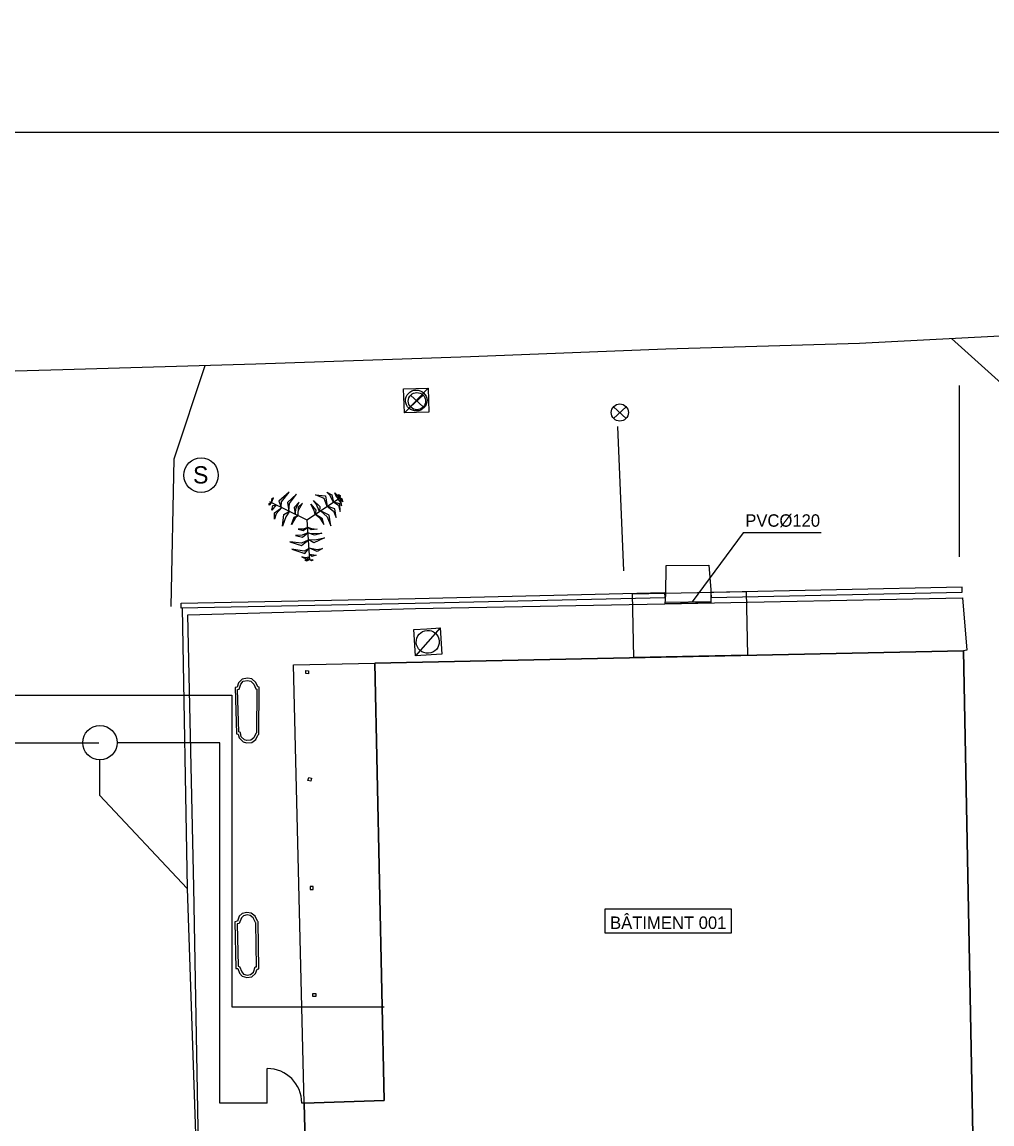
# Model space of a CAD drawing. Extents: x 37864 to 38032, y 453991 to 454052.
# Drawn here: x 37980.79 to 38008.9, y 454019.49 to 454051.41 of the extents above; entities that cross this region are included whole.
import ezdxf

# ---------------------------------------------------------------- set-up
doc = ezdxf.new("R2010")
doc.units = 0
for name, color, linetype in [('GO MUR EXTERIEUR', 7, 'Continuous'), ('GO_MUR_INTERIEUR', 7, 'Continuous'), ('PS_Bolt', 7, 'Continuous'), ('PS_Const', 7, 'Continuous'), ('PS_Dim', 7, 'Continuous'), ('PS_Elev_flag', 7, 'Continuous'), ('PS_Hatch', 7, 'Continuous'), ('PS_Hidden', 7, 'Continuous'), ('PS_Mid', 7, 'Continuous'), ('PS_Plate', 7, 'Continuous'), ('PS_Solid', 7, 'Continuous'), ('PS_Text', 7, 'Continuous'), ('SO_MENUISERIE EXT DOR', 7, 'Continuous'), ('SO_MENUISERIE INT DOR', 7, 'Continuous'), ('SO_SANITAIRE DETAILLE', 7, 'Continuous')]:
    doc.layers.add(name, color=color, linetype=linetype)

# ---------------------------------------------------------------- blocks, each defined once
blk = doc.blocks.new('PANNEAU')
blk.add_circle((0, 0), 0.5)
blk.add_text('S', height=0.5).set_placement((-0.233, -0.24))
blk = doc.blocks.new('A-REGARD')
for p, q in [((0, 1), (1, 1)), ((0, 0), (1, 1)), ((0, 0), (0, 1)), ((1, 1), (1, 0)), ((0.5, 0), (0, 0)), ((1, 0), (0.5, 0))]:
    blk.add_line(p, q)
blk.add_circle((0.5, 0.5), 0.438)
blk = doc.blocks.new('CONIFERE')
for p, q in [((0, 0), (0.976, 0.647)), ((-1.078, 0.532), (0, 0)), ((0, 0), (0.08, -1.165))]:
    blk.add_line(p, q)
for points in [[(-0.741, 0.364), (-0.739, 0.523), (-0.511, 0.797), (-0.811, 0.54)], [(-0.519, 0.261), (-0.499, 0.472), (-0.295, 0.746), (-0.559, 0.501)], [(0.588, 0.387), (0.498, 0.618), (0.255, 0.727), (0.538, 0.69)], [(0.768, 0.507), (0.663, 0.715), (0.579, 0.797), (0.722, 0.721)], [(0.913, 0.604), (0.84, 0.707), (0.816, 0.777), (0.899, 0.693)], [(0.956, 0.633), (0.917, 0.732), (0.966, 0.705)], [(-1.023, 0.503), (-1.089, 0.42), (-1.091, 0.475)], [(-1.025, 0.504), (-0.971, 0.637), (-1.021, 0.589)], [(-0.888, 0.436), (-1.016, 0.279), (-0.985, 0.411)], [(-0.721, 0.354), (-0.891, 0.168), (-0.941, 0.021), (-0.939, 0.198)], [(-0.335, 0.164), (-0.311, 0.342), (-0.22, 0.506), (-0.364, 0.356)], [(-0.262, 0.122), (-0.241, 0.278), (-0.128, 0.485), (-0.248, 0.367)], [(0.245, 0.158), (0.215, 0.27), (0.111, 0.452), (0.259, 0.279)], [(0.371, 0.242), (0.267, 0.463), (0.197, 0.562), (0.378, 0.385)], [(0.59, 0.394), (0.775, 0.253), (0.851, 0.066), (0.809, 0.322)], [(0.782, 0.51), (0.919, 0.422), (0.966, 0.236), (0.956, 0.46)], [(0.907, 0.587), (0.977, 0.501), (1.009, 0.403), (0.992, 0.558)], [(0.958, 0.634), (1.046, 0.52), (1.029, 0.588)], [(-0.506, 0.248), (-0.606, 0.089), (-0.702, -0.183), (-0.666, 0.155)], [(-0.256, 0.125), (-0.338, 0.043), (-0.443, -0.139), (-0.368, 0.076)], [(0.246, 0.164), (0.37, 0.069), (0.493, -0.134), (0.451, 0.03)], [(0.394, 0.257), (0.593, 0.086), (0.691, -0.173), (0.65, 0.13)], [(0.018, -0.223), (-0.1, -0.27), (-0.255, -0.267), (-0.103, -0.306)], [(0.018, -0.218), (0.131, -0.256), (0.297, -0.27), (0.128, -0.295)], [(0.037, -0.588), (-0.156, -0.676), (-0.495, -0.637), (-0.152, -0.743)], [(0.029, -0.381), (-0.138, -0.448), (-0.325, -0.452), (-0.124, -0.502)], [(0.029, -0.376), (0.157, -0.398), (0.437, -0.392), (0.22, -0.442)], [(0.041, -0.571), (0.229, -0.578), (0.512, -0.525), (0.202, -0.663)], [(0.058, -0.832), (-0.08, -0.91), (-0.431, -0.849), (-0.059, -0.981)], [(0.057, -0.81), (0.303, -0.864), (0.456, -0.834), (0.301, -0.92)], [(0.064, -1.081), (-0.046, -1.098), (-0.147, -1.076), (-0.004, -1.14)], [(0.079, -1.149), (-0.063, -1.168), (0.004, -1.187)], [(0.069, -0.995), (0.269, -1.028), (0.14, -1.067)], [(0.079, -1.146), (0.184, -1.162), (0.137, -1.191)]]:
    blk.add_lwpolyline(points, close=True)
blk = doc.blocks.new('BORNANTI')
for p, q in [((-0.369, -0.338), (0.369, 0.338)), ((-0.369, 0.338), (0.369, -0.338))]:
    blk.add_line(p, q)
blk.add_circle((0, 0), 0.5)
blk = doc.blocks.new('DIVERS-P')
blk.add_circle((0, 0), 0.5)

msp = doc.modelspace()

# ---------------------------------------------------------------- linework, layer by layer
at = {"layer": 'DEFPOINTS'}
msp.add_lwpolyline([(37950.431, 453990.816), (38032.431, 453990.816), (38032.431, 454048.216), (37950.431, 454048.216)], close=True, dxfattribs=at)
at = {"layer": 'GO MUR EXTERIEUR'}
for points in [[(37991.018, 454032.841), (37991.287, 454020.167), (37988.97, 454020.093), (37989.052, 454016.74), (38008.383, 454017.171), (38008.074, 454033.195)], [(37997.689, 454025.723), (38001.343, 454025.723), (38001.343, 454025.015), (37997.689, 454025.015)]]:
    msp.add_lwpolyline(points, close=True, dxfattribs=at)
at = {"layer": 'GO_MUR_INTERIEUR'}
msp.add_line((37999.44, 454034.608), (38000.76, 454034.623), dxfattribs=at)
msp.add_lwpolyline([(37985.426, 454034.436), (37985.576, 454026.312), (37985.9, 454016.645)], dxfattribs=at)
at = {"layer": 'PS_Bolt'}
for points in [[(37987.656, 454030.778), (37987.662, 454032.142), (37987.619, 454032.154), (37987.563, 454032.273), (37987.45, 454032.381), (37987.322, 454032.405), (37987.166, 454032.378), (37987.066, 454032.264), (37987.026, 454032.143), (37986.962, 454032.132), (37987.003, 454030.793), (37987.056, 454030.777), (37987.08, 454030.67), (37987.201, 454030.554), (37987.298, 454030.525), (37987.447, 454030.541), (37987.564, 454030.626), (37987.622, 454030.756), (37987.656, 454030.778)], [(37987.034, 454032.074), (37987.079, 454032.082), (37987.128, 454032.228), (37987.202, 454032.313), (37987.321, 454032.334), (37987.417, 454032.316), (37987.505, 454032.232), (37987.569, 454032.094), (37987.592, 454032.088), (37987.586, 454030.816), (37987.567, 454030.804), (37987.508, 454030.672), (37987.421, 454030.609), (37987.305, 454030.596), (37987.238, 454030.616), (37987.144, 454030.706), (37987.116, 454030.832), (37987.072, 454030.845), (37987.034, 454032.074)], [(37987.636, 454025.348), (37987.615, 454025.367), (37987.543, 454025.51), (37987.432, 454025.594), (37987.308, 454025.614), (37987.168, 454025.583), (37987.085, 454025.503), (37987.031, 454025.358), (37986.955, 454025.34), (37986.984, 454023.996), (37987.045, 454023.987), (37987.096, 454023.857), (37987.169, 454023.766), (37987.306, 454023.726), (37987.445, 454023.753), (37987.559, 454023.847), (37987.599, 454023.975), (37987.653, 454023.986), (37987.636, 454025.348)], [(37987.567, 454025.317), (37987.559, 454025.324), (37987.488, 454025.464), (37987.403, 454025.528), (37987.31, 454025.543), (37987.203, 454025.519), (37987.145, 454025.463), (37987.083, 454025.298), (37987.026, 454025.285), (37987.053, 454024.057), (37987.096, 454024.05), (37987.157, 454023.892), (37987.21, 454023.827), (37987.31, 454023.798), (37987.414, 454023.818), (37987.498, 454023.888), (37987.545, 454024.036), (37987.582, 454024.043), (37987.567, 454025.317)]]:
    msp.add_lwpolyline(points, dxfattribs=at)
at = {"layer": 'PS_Dim'}
for p, q in [((37977.069, 454030.534), (37983.015, 454030.534)), ((37986.521, 454030.534), (37983.562, 454030.534)), ((37986.521, 454020.093), (37986.521, 454030.534)), ((37987.897, 454020.093), (37987.897, 454021.093)), ((37987.897, 454020.093), (37986.521, 454020.093)), ((37989.043, 454020.093), (37988.897, 454020.093))]:
    msp.add_line(p, q, dxfattribs=at)
msp.add_arc((37987.897, 454020.093), 1, 360, 90, dxfattribs=at)
at = {"layer": 'PS_Hatch'}
msp.add_lwpolyline([(37998.478, 454034.846), (38001.777, 454034.915), (38001.816, 454033.065), (37998.516, 454032.997)], close=True, dxfattribs=at)
msp.add_lwpolyline([(37988.97, 454020.093), (37988.657, 454032.792), (37991.018, 454032.841), (37991.287, 454020.167), (37988.97, 454020.093)], dxfattribs=at)
at = {"layer": 'PS_Hidden'}
msp.add_lwpolyline([(37973.328, 454031.906), (37986.869, 454031.906), (37986.869, 454022.877), (37991.287, 454022.877)], dxfattribs=at)
at = {"layer": 'PS_Mid'}
for points in [[(37999.461, 454035.67), (38000.697, 454035.675), (38000.756, 454034.958), (38000.748, 454034.585), (37999.426, 454034.558), (37999.449, 454034.829), (37999.461, 454035.67)], [(37989.052, 454016.74), (37988.897, 454016.739), (37985.942, 454016.672), (37985.764, 454026.348), (37985.598, 454034.242), (37992.193, 454034.425), (37999.415, 454034.558), (38008.043, 454034.732), (38008.168, 454033.217), (38008.074, 454033.195)]]:
    msp.add_lwpolyline(points, dxfattribs=at)
at = {"layer": 'PS_Solid'}
msp.add_lwpolyline([(38000.758, 454034.736), (38008.037, 454034.892), (38008.034, 454035.042), (38000.755, 454034.886)], close=True, dxfattribs=at)
for points in [[(37985.397, 454034.578), (37992.181, 454034.715), (37999.412, 454034.884), (37999.416, 454034.734), (37992.184, 454034.565), (37985.4, 454034.428), (37985.397, 454034.578)], [(38008.074, 454033.195), (38008.383, 454017.171), (37989.052, 454016.74), (37988.97, 454020.093), (37991.287, 454020.167), (37991.018, 454032.841), (38008.074, 454033.195)]]:
    msp.add_lwpolyline(points, dxfattribs=at)
at = {"layer": 'PS_Text'}
for points in [[(37989.017, 454032.624), (37989.095, 454032.617), (37989.087, 454032.527), (37989.009, 454032.534)], [(37989.096, 454029.522), (37989.182, 454029.502), (37989.161, 454029.415), (37989.076, 454029.434)], [(37989.14, 454026.281), (37989.226, 454026.279), (37989.228, 454026.369), (37989.142, 454026.371)], [(37989.216, 454023.268), (37989.302, 454023.27), (37989.304, 454023.18), (37989.218, 454023.178)]]:
    msp.add_lwpolyline(points, close=True, dxfattribs=at)
at = {"layer": 'SO_MENUISERIE INT DOR'}
msp.add_lwpolyline([(38003.952, 454036.616), (38001.691, 454036.616), (38000.212, 454034.617)], dxfattribs=at)
at = {"layer": 'SO_SANITAIRE DETAILLE'}
for p, q in [((38007.957, 454035.922), (38007.956, 454040.88)), ((37998.227, 454035.515), (37998.06, 454039.692)), ((37983.035, 454030.034), (37983.035, 454029.009)), ((37983.035, 454029.009), (37985.576, 454026.312))]:
    msp.add_line(p, q, dxfattribs=at)
for points in [[(38017.828, 454051.412), (38017.827, 454048.283), (38017.43, 454042.806), (38015.386, 454042.628), (38010.805, 454042.4), (38005.064, 454042.102), (37999.448, 454041.936), (37993.784, 454041.715), (37987.562, 454041.497), (37981.968, 454041.336), (37975.041, 454041.141), (37971.132, 454041.024), (37964.54, 454040.907), (37959.445, 454041.057), (37952.881, 454040.532)], [(38007.728, 454042.24), (38010.805, 454039.473), (38014.757, 454036.508), (38018.237, 454034.006), (38021.012, 454032.123), (38024.325, 454030.315)], [(37986.088, 454041.454), (37985.191, 454038.745), (37985.104, 454034.476)]]:
    msp.add_lwpolyline(points, dxfattribs=at)

# ---------------------------------------------------------------- block references
at = {"layer": 'PS_Bolt', "xscale": 0.5000000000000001, "yscale": 0.5, "rotation": 2.2526485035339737e-05}
for p in [(37992.233, 454040.429), (37998.114, 454040.099)]:
    msp.add_blockref('BORNANTI', p, dxfattribs=at)
at = {"layer": 'PS_Const', "rotation": 2.2526485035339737e-05}
msp.add_blockref('CONIFERE', (37989.043, 454036.991), dxfattribs=at)
at = {"layer": 'PS_Elev_flag', "rotation": 2.2526485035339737e-05}
msp.add_blockref('PANNEAU', (37985.977, 454038.283), dxfattribs=at)
at = {"layer": 'PS_Plate', "rotation": 2.2526485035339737e-05}
msp.add_blockref('DIVERS-P', (37983.047, 454030.534), dxfattribs=at)
at = {"layer": 'SO_MENUISERIE EXT DOR'}
for p, xscale, yscale, rotation in [((37991.869, 454040.088), 0.7140624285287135, 0.6935784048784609, 1.9842813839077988), ((37992.905, 454033.859), 0.7636120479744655, 0.7597857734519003, -176.444621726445)]:
    msp.add_blockref('A-REGARD', p, dxfattribs=dict(at, xscale=xscale, yscale=yscale, rotation=rotation))

# ---------------------------------------------------------------- texts
at = {"layer": 'PS_Hidden'}
msp.add_text('BÂTIMENT 001', height=0.36, rotation=360, dxfattribs=at).set_placement((37997.832, 454025.138))
at = {"layer": 'SO_MENUISERIE INT DOR'}
msp.add_text('PVC%%C120', height=0.36, rotation=0, dxfattribs=at).set_placement((38001.75, 454036.79))

doc.saveas('drawing.dxf')
